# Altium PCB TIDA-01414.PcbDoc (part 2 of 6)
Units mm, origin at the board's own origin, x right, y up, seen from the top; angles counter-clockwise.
Board outline 400 x 135 mm, 4 copper layers (Top Copper, Copper Layer 2, Copper Layer 3, Bottom Copper), stack 1.567 mm thick; 835 components, 519 nets, 2420 pads, 2045 vias.
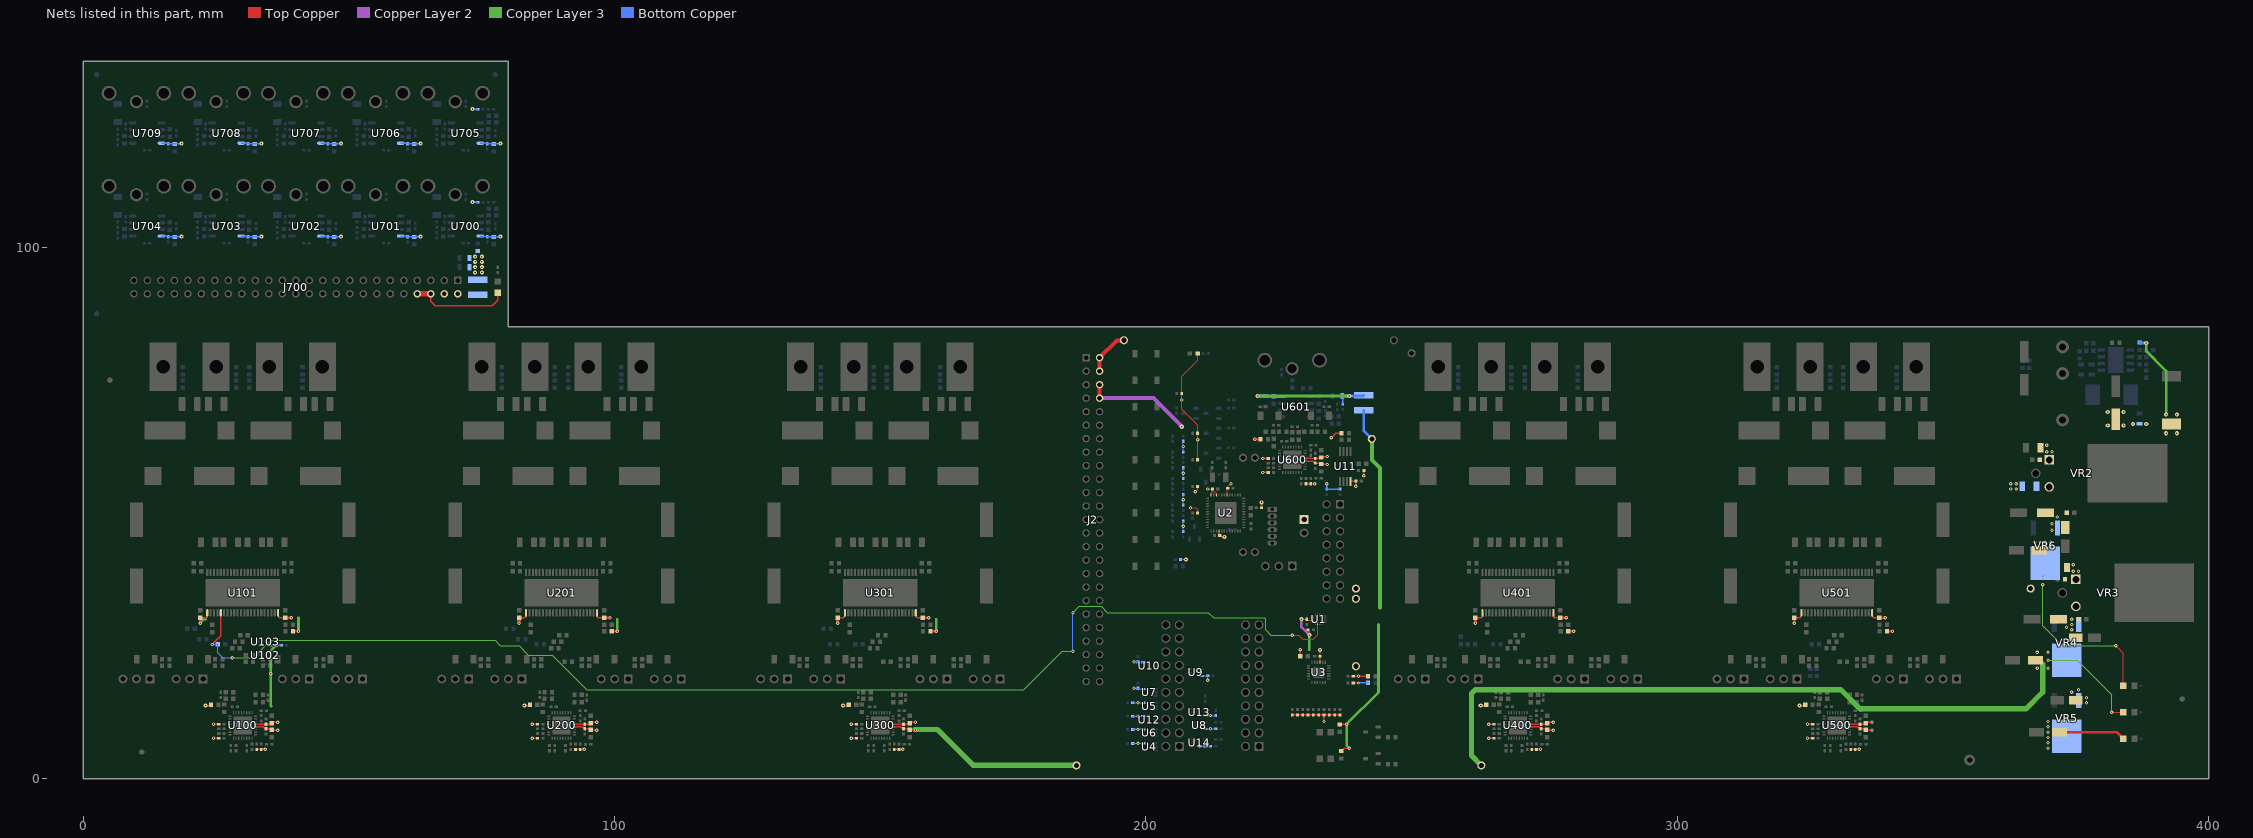
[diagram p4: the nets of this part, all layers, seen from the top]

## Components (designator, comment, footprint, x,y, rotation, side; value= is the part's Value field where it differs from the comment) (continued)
R705 "ERJ-2RKF1002X" 0402L 66.5,104.25 r90 bottom
R706 "ERJ-2RKF1002X" 0402L 51.5,104.25 r90 bottom locked
R707 "ERJ-2RKF1002X" 0402L 36.5,104.25 r90 bottom
R708 "ERJ-2RKF1002X" 0402L 21.5,104.25 r90 bottom
R709 "ERJ-2RKF1002X" 0402L 6.5,104.25 r90 bottom
R710 "ERJ-2RKF1002X" 0402L 72,100.75 r0 bottom
R711 "ERJ-2RKF1002X" 0402L 57,100.75 r0 bottom
R712 "ERJ-2RKF1002X" 0402L 42,100.75 r0 bottom
R713 "ERJ-2RKF1002X" 0402L 27,100.75 r0 bottom
R714 "ERJ-2RKF1002X" 0402L 12,100.75 r0 bottom
R715 "ERJ-2RKF1002X" 0402L 77.5,104 r90 bottom
R716 "ERJ-2RKF1002X" 0402L 62.5,104 r90 bottom locked
R717 "ERJ-2RKF1002X" 0402L 47.5,104 r90 bottom
R718 "ERJ-2RKF1002X" 0402L 32.5,104 r90 bottom
R719 "ERJ-2RKF1002X" 0402L 17.5,104 r90 bottom
R720 "ERJ-2RKF1002X" 0402L 66.5,119.75 r90 bottom
R721 "ERJ-2RKF1002X" 0402L 51.5,119.75 r90 bottom
R722 "ERJ-2RKF1002X" 0402L 36.5,119.75 r90 bottom
R723 "ERJ-2RKF1002X" 0402L 21.5,119.75 r90 bottom
R724 "ERJ-2RKF1002X" 0402L 6.5,119.75 r90 bottom
R725 "ERJ-2RKF1002X" 0402L 66.5,121.75 r90 bottom
R726 "ERJ-2RKF1002X" 0402L 51.5,121.75 r90 bottom
R727 "ERJ-2RKF1002X" 0402L 36.5,121.75 r90 bottom
R728 "ERJ-2RKF1002X" 0402L 21.5,121.75 r90 bottom
R729 "ERJ-2RKF1002X" 0402L 6.5,121.75 r90 bottom
R730 "ERJ-2RKF1002X" 0402L 72,118.25 r0 bottom
R731 "ERJ-2RKF1002X" 0402L 57,118.25 r0 bottom
R732 "ERJ-2RKF1002X" 0402L 42,118.25 r0 bottom
R733 "ERJ-2RKF1002X" 0402L 27,118.25 r0 bottom
R734 "ERJ-2RKF1002X" 0402L 12,118.25 r0 bottom
R735 "ERJ-2RKF1002X" 0402L 77.5,121.5 r90 bottom
R736 "ERJ-2RKF1002X" 0402L 62.5,121.5 r90 bottom
R737 "ERJ-2RKF1002X" 0402L 47.5,121.5 r90 bottom
R738 "ERJ-2RKF1002X" 0402L 32.5,121.5 r90 bottom
R739 "ERJ-2RKF1002X" 0402L 17.5,121.5 r90 bottom
R740 "ERJ-2RKF1002X" 0402L 74.75,108.5 r0 bottom
R741 "ERJ-2RKF1002X" 0402L 74.75,126 r0 bottom
R742 "ERJ-2RKF1002X" 0402L 76.75,108.5 r0 bottom
R743 "ERJ-2RKF1002X" 0402L 76.75,126 r0 bottom
R744 "CRCW0402100KFKED" 0402L 72,109.5 r90 bottom
R745 "CRCW0402100KFKED" 0402L 57,109.5 r90 bottom locked
R746 "CRCW0402100KFKED" 0402L 42,109.5 r90 bottom
R747 "CRCW0402100KFKED" 0402L 27,109.5 r90 bottom
R748 "CRCW0402100KFKED" 0402L 12,109.5 r90 bottom
R749 "CRCW0402100KFKED" 0402L 72,127 r90 bottom
R750 "CRCW0402100KFKED" 0402L 57,127 r90 bottom
R751 "CRCW0402100KFKED" 0402L 42,127 r90 bottom
R752 "CRCW0402100KFKED" 0402L 27,127 r90 bottom
R753 "CRCW0402100KFKED" 0402L 12,127 r90 bottom
R754 "CRCW0402360RJNED" 0402L 78,95.75 r90 top
RESET "TL1015AF160QG" SW_TL1015AF160QG 200,40 r180 top
SL+ "Surround Left+" TEC-SpadeLug_63066-1 45,77.5 r90 top
SL- "Surround Left-" TEC-SpadeLug_63066-1 35,77.5 r90 top
SR+ "Surround Right+" TEC-SpadeLug_63066-1 25,77.5 r90 top
SR- "Surround Right-" TEC-SpadeLug_63066-1 15,77.5 r90 top
SUBOUT "RCJ-024" CONN_RCJ-024 227.5,78.75 r180 top locked
SURROUND-LEFT "RCJ-024" CONN_RCJ-024 70,111.5 r180 top locked
SURROUND-RIGHT "RCJ-024" CONN_RCJ-024 70,129 r180 top locked
TP1 "FAULT" Keystone5003#1 355,3.5 r0 top
TP2 "CLIP" Keystone5003#2 372.5,67.5 r0 top
U1 "TCA6408ARSVR" RSV0016A 232.5,30 r90 top
U2 "MSP430F5234IRGZT" RGZ0048B 215,50 r270 top
U3 "TCA9548ARGER" RGE0024C 232.5,20 r0 top
U4 "LVC1G125" DCK0005A_N 200.625,6 r180 bottom
U5 "LVC1G125" DCK0005A_N 200.625,13.625 r180 bottom
U6 "LVC1G125" DCK0005A_N 200.625,8.625 r180 bottom
U7 "LVC1G125" DCK0005A_N 200.625,16.25 r180 bottom
U8 "LVC1G125" DCK0005A_N 210,10 r0 bottom
U9 "LVC1G125" DCK0005A_N 209.375,20 r0 bottom
U10 "LVC1G125" DCK0005A_N 200.6,21.25 r180 bottom
U11 "24LC512-I/ST" TSSOP-8 237.5,58.75 r270 top
U12 "LVC1G125" DCK0005A_N 200.625,11.125 r180 bottom
U13 "LVC1G125" DCK0005A_N 210,12.5 r0 bottom
U14 "LVC1G125" DCK0005A_N 210,6.75 r0 bottom
U100 "PCM5252RHBR" RHB0032E 30,10 r180 top locked
U101 "TPA3244DDWR" DDW0044D_N 30,35 r90 top locked
U102 "LVC1G125" DCK0005A_N 34.25,23.25 r0 bottom
U103 "LVC1G125" DCK0005A_N 34.25,25.75 r0 bottom
U200 "PCM5252RHBR" RHB0032E 90,10 r180 top locked
U201 "TPA3244DDWR" DDW0044D_N 90,35 r90 top
U300 "PCM5252RHBR" RHB0032E 150,10 r180 top locked
U301 "TPA3244DDWR" DDW0044D_N 150,35 r90 top
U400 "PCM5252RHBR" RHB0032E 270,10 r180 top locked
U401 "TPA3244DDWR" DDW0044D_N 270,35 r90 top
U500 "PCM5252RHBR" RHB0032E 330,10 r180 top
U501 "TPA3244DDWR" DDW0044D_N 330,35 r90 top
U600 "PCM5252RHBR" RHB0032E 227.5,60 r180 top
U601 "NE5532AD" D0008A_N 228.25,70 r180 bottom
U700 "NE5532AD" D0008A_N 72,104 r0 bottom
U701 "NE5532AD" D0008A_N 57,104 r0 bottom locked
U702 "NE5532AD" D0008A_N 42,104 r0 bottom
U703 "NE5532AD" D0008A_N 27,104 r0 bottom
U704 "NE5532AD" D0008A_N 12,104 r0 bottom
U705 "NE5532AD" D0008A_N 72,121.5 r0 bottom
U706 "NE5532AD" D0008A_N 57,121.5 r0 bottom
U707 "NE5532AD" D0008A_N 42,121.5 r0 bottom
U708 "NE5532AD" D0008A_N 27,121.5 r0 bottom
U709 "NE5532AD" D0008A_N 12,121.5 r0 bottom
UPL+ "Up Left+" TEC-SpadeLug_63066-1 105,77.5 r90 top
UPL- "Up Left-" TEC-SpadeLug_63066-1 95,77.5 r90 top
UPMIX-LEFT "RCJ-024" CONN_RCJ-024 55,111.5 r180 top locked
UPMIX-RIGHT "RCJ-024" CONN_RCJ-024 55,129 r180 top locked
UPR+ "Up Right+" TEC-SpadeLug_63066-1 85,77.5 r90 top
UPR- "Up Right-" TEC-SpadeLug_63066-1 75,77.5 r90 top
USB-I2X "PPPC082LFBN-RC" Sullins_xPxC082LFBN 235.25,42.75 r270 top
VOL-DN "" SW_TL1015AF160QG 200,70 r0 top
VOL-UP "" SW_TL1015AF160QG 200,75 r0 top
VR1 "TPS54340DDAR" DDA0008E_N 382.5,78.75 r0 bottom
VR2 "LM2940CT-12/NOPB" TO-220AB_Horizontal_100mil 370,60 r270 top locked
VR3 "LM2940CT-12/NOPB" TO-220AB_Horizontal_100mil 375,37.5 r270 top locked
VR4 "TLV1117-33IKVURG3" KVU0003A_N 373.25,24.75 r270 bottom
VR5 "TLV1117-33IKVURG3" KVU0003A_N 373.25,10.5 r270 bottom
VR6 "TLV1117-33IKVURG3" KVU0003A_N 369.25,43 r270 bottom
Y2 "NX3215SA-32.768K-STD-MUA-8" XTAL_NX3215SA 213.75,56.75 r180 top
ZZ1 "These assemblies must comply with workmanship standards IPC-A-610 Class 2, unless otherwise specified." AssemblyNote 4.25,140 r0 top
ZZ2 "These assemblies are ESD sensitive, ESD precautions shall be observed." AssemblyNote 4.25,144 r0 top
ZZ3 "These assemblies must be clean and free from flux and all contaminants. Use of no clean flux is not acceptable." AssemblyNote 4.25,142 r0 top

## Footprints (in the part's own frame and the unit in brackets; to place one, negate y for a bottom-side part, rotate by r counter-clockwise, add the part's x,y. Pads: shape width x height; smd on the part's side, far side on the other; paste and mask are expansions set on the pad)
3M_923345-20-C [mil] "Jumper Wire, 2\" Spacing, Red, Pkg of 100"
  round 60 hole 38: 1(-1000,0) 2(1000,0)
  silkscreen extent -970,-32 970,32, body extent -1015,-29 1013,29, height 79
3M_923345-30-C [mil] "Jumper Wire, 3\" Spacing, Orange, Pkg of 75"
  round 60 hole 38: 1(-1500,0) 2(1500,0)
  silkscreen extent -1470,-32 1470,32, body extent -1515,-27 1517,31, height 79
3M_923345-50-C [mil] "Jumper Wire, 5\" Spacing, Green, Pkg of 75"
  round 60 hole 38: 1(-2500,0) 2(2500,0)
  silkscreen extent -2470,-32 2470,32, body extent -2516,-29 2515,30, height 79
3M_N2550-6002-RB [mm] "Header, 2.54mm, 25x2, TH"
  rect 1.4x1.4 hole 0.89: 1(-1.27,30.48)
  round 1.4 hole 0.89: 2(1.27,30.48) 3(-1.27,27.94) 4(1.27,27.94) 5(-1.27,25.4) 6(1.27,25.4) 7(-1.27,22.86) 8(1.27,22.86) 9(-1.27,20.32) 10(1.27,20.32) 11(-1.27,17.78) 12(1.27,17.78) 13(-1.27,15.24) 14(1.27,15.24) 15(-1.27,12.7) 16(1.27,12.7) 17(-1.27,10.16) 18(1.27,10.16) 19(-1.27,7.62) 20(1.27,7.62) 21(-1.27,5.08) 22(1.27,5.08) 23(-1.27,2.54) 24(1.27,2.54) 25(-1.27,0) 26(1.27,0) 27(-1.27,-2.54) 28(1.27,-2.54) 29(-1.27,-5.08) 30(1.27,-5.08) 31(-1.27,-7.62) 32(1.27,-7.62) 33(-1.27,-10.16) 34(1.27,-10.16) 35(-1.27,-12.7) 36(1.27,-12.7) 37(-1.27,-15.24) 38(1.27,-15.24) 39(-1.27,-17.78) 40(1.27,-17.78) 41(-1.27,-20.32) 42(1.27,-20.32) 43(-1.27,-22.86) 44(1.27,-22.86) 45(-1.27,-25.4) 46(1.27,-25.4) 47(-1.27,-27.94) 48(1.27,-27.94) 49(-1.27,-30.48) 50(1.27,-30.48)
  silkscreen extent -4.5,-35.41 4.52,35.41, body extent -4.11,-35.41 4.52,35.41, height 9.92
0402L [mm] "0402 from SM-752 data"
  rect 0.6x0.5 smd: 1(-0.5,0) 2(0.5,0)
  body extent -0.55,-0.3 0.55,0.3, height 0.6
0603L [mm] "0603 from SM-752 data"
  rect 0.8x0.85 smd: 1(-0.7,0) 2(0.7,0)
  silkscreen extent -0.07,-0.33 0.07,0.33, body extent -0.87,-0.47 0.87,0.47, height 1
0805_KTR [mm] "ROHM"
  rect 0.7x1.15 smd: 1(-0.95,0) 2(0.95,0)
  silkscreen extent -0.35,-0.7 0.35,0.7, body extent -1.05,-0.67 1.05,0.67, height 0.65
1206_180 [mm] "1206_180"
  rect 1.1x1.6 smd: 1(-1.7,0) 2(1.7,0)
  silkscreen extent -0.9,-1 0.9,1, body extent -1.75,-0.95 1.75,0.95, height 1.8
1206_180L [mm] "1206_180"
  rect 1.1x1.75 smd: 1(-1.35,0) 2(1.35,0)
  silkscreen extent -0.4,-0.77 0.4,0.77, body extent -1.75,-0.95 1.75,0.95, height 1.8
1206L [mm] "1206 from SM-752 data"
  rect 1.1x1.75 smd: 1(-1.35,0) 2(1.35,0)
  silkscreen extent -0.4,-0.77 0.4,0.77, body extent -1.7,-0.9 1.7,0.9, height 1.35
1210_220 [mm] "1210"
  rect 1.3x2.7 smd: 1(-1.45,0) 2(1.45,0)
  silkscreen extent -2.32,-1.57 2.32,1.57, body extent -1.7,-1.35 1.7,1.35, height 2.2
AssemblyNote [mm] "Assembly Note"
Bivar_9912-250 [mm] "NYLON TUBE SPACER"
  body extent -3.17,-3.17 3.17,3.18, height 22.22
Coilcraft_RA7231-ALB [mm] "SMD, 4-Leads, Body 15.5x14mm"
  rect 7.7x3.4 smd: 1(-4.65,4.3) 3(4.65,-4.3)
  rect 3.2x3.4 smd: 2(-6.9,-4.3) 4(6.9,4.3)
  silkscreen extent -7.75,-7 7.75,7.4, body extent -7.75,-7 7.75,7, height 15.99
CONN_923345-07-C [mil] "3M, Wire jumper, 700 mil lenght, Violet"
  round 60 hole 37: 1(-350,0) 2(350,0)
  silkscreen extent -315,-35 315,31, body extent -363,-33 363,33, height 74
CONN_RCJ-024 [mm] "RCA Jack, Vertical, Yellow, TH"
  round 2.5 hole 1.7: 1(0,1.6)
  round 2.8 hole 2: 2(-5.15,0) 3(5.15,0)
  silkscreen extent -5.26,-5.1 5.46,4.9, body extent -6.38,-5.1 6.58,4.9, height 15.95
D0008A_N [mm] "SOIC, 8-Leads, Body 4.9x3.9mm, Pitch 1.27mm, IPC Medium Density"
  oval 1.45x0.6 smd: 1(-2.725,1.905) 2(-2.725,0.635) 3(-2.725,-0.635) 4(-2.725,-1.905) 5(2.725,-1.905) 6(2.725,-0.635) 7(2.725,0.635) 8(2.725,1.905)
  silkscreen extent -3.3,-2.5 0.9,2.5, body extent -3,-2.45 3,2.45, height 1.63
DCK0005A_N [mm] "SOT353, 5-Leads, Body 2x1.3mm, Pitch 0.65mm, Lead Span 2.1mm, IPC Medium Density"
  rrect25% 0.85x0.4 smd: 1(-1.125,0.65) 2(-1.125,0) 3(-1.125,-0.65) 4(1.125,-0.65) 5(1.125,0.65)
  silkscreen extent -1.48,-1.02 0.55,1.1, body extent -1.14,-1 1.14,1, height 0.95
DDA0008E_N [mm]
  rrect17% 1.45x0.6 smd: 1(-2.725,1.905) 2(-2.725,0.635) 3(-2.725,-0.635) 4(-2.725,-1.905) 5(2.725,-1.905) 6(2.725,-0.635) 7(2.725,0.635) 8(2.725,1.905)
  rrect7% 2.95x4.9 smd paste-1.5 mask-1.5: 9(0,0)
  rrect4% 2.4x3.1 on Bottom Paste: 9(0,0)
  rrect4% 2.4x3.1 on Bottom Solder: 9(0,0)
  silkscreen extent -3.22,-2.5 1.4,2.5, body extent -3,-2.45 3,2.45, height 1.57
DDW0044D_N [mm] "SOP, 44-Leads, Body 14.1x6.2mm, Pitch 0.635mm, IPC Medium Density"
  rrect100% 1.4x0.4 smd: 1(-3.8,6.667) 2(-3.8,6.032) 3(-3.8,5.397) 4(-3.8,4.763) 5(-3.8,4.127) 6(-3.8,3.492) 7(-3.8,2.857) 8(-3.8,2.222) 9(-3.8,1.587) 10(-3.8,0.952) 11(-3.8,0.317) 12(-3.8,-0.318) 13(-3.8,-0.953) 14(-3.8,-1.588) 15(-3.8,-2.223) 16(-3.8,-2.858) 17(-3.8,-3.492) 18(-3.8,-4.127) 19(-3.8,-4.763) 20(-3.8,-5.398) 21(-3.8,-6.033) 22(-3.8,-6.668) 23(3.8,-6.668) 24(3.8,-6.033) 25(3.8,-5.398) 26(3.8,-4.763) 27(3.8,-4.127) 28(3.8,-3.492) 29(3.8,-2.857) 30(3.8,-2.222) 31(3.8,-1.587) 32(3.8,-0.952) 33(3.8,-0.317) 34(3.8,0.318) 35(3.8,0.953) 36(3.8,1.588) 37(3.8,2.223) 38(3.8,2.858) 39(3.8,3.492) 40(3.8,4.127) 41(3.8,4.763) 42(3.8,5.397) 43(3.8,6.032) 44(3.8,6.667)
  rrect4% 5.2x14 smd paste-3 mask-3: 45(0,0)
  rrect2% 4.43x7.3 on Top Paste: 45(0,0)
  rrect2% 4.43x7.3 on Top Solder: 45(0,0)
  silkscreen extent -4.35,-7.05 2.7,7.12, body extent -4.06,-7 4.06,7, height 1
FCC_disclaimer_stacked [mm]
Fiducial10-20 [mm]
  round 1 smd mask+0.5: 1(0,0)
  Top Copper keep-out circle w1.178: c0,0 r0.5
Keystone5000 [mil] "For Keystone 500x miniature loop terminals"
  round 95 hole 50: 1(0,0)
  silkscreen extent -58,-58 58,58, body extent -49,-49 49,49, height 182
Keystone5001 [mil] "For Keystone 500x miniature loop terminals"
  round 95 hole 50: 1(0,0)
  silkscreen extent -58,-58 58,58, body extent -49,-49 49,49, height 182
Keystone5003#1 [mil] "For Keystone 500x miniature loop terminals"
  round 80 hole 40: 1(0,0)
  silkscreen extent -58,-58 58,58, body extent -49,-49 49,49, height 182
Keystone5003#2 [mil] "For Keystone 500x miniature loop terminals"
  round 95 hole 50: 1(0,0)
  silkscreen extent -58,-58 58,58, body extent -49,-49 49,49, height 182
Keystone_3205 [mm] "Flat Nylon Washer"
  body extent -3.96,-3.96 3.96,3.96, height 1.57
KVU0003A_N [mm] "DPAK, 3-Leads, Body 6.6x6.1mm, Pitch 2.29mm, IPC Medium Density"
  rrect10% 2.8x1 smd: 1(-4.2,2.29) 3(-4.2,-2.29)
  rrect2% 6.3x5.55 smd: 4(2.5,0)
  silkscreen extent -4.35,-3.35 -1.05,3.46, body extent -5.06,-3.3 5.06,3.3, height 2.39
LED_LTST-C170_Red [mm] "LITE-ON"
  rect 1.2x1.2 smd: 1(-1.05,0) 2(1.05,0)
  silkscreen extent -1.6,-1 2.2,1, body extent -1.05,-0.67 1.05,0.67, height 1.1
LED_LTST-C171 [mm] "LITE-ON"
  rect 1.2x1.2 smd: 1(-1.05,0) 2(1.05,0)
  silkscreen extent -1.6,-1 2.2,1, body extent -1.05,-0.67 1.05,0.67, height 0.8
LED_LTST-C190_Red [mm] "Lite-On"
  rect 0.8x0.8 smd: 1(-0.75,0) 2(0.75,0)
  silkscreen extent -1.1,-0.8 1.8,0.8, body extent -0.85,-0.45 0.85,0.45, height 0.9
LED_SMLP12_BLUE [mm] "Rohm Semiconductor"
  rect 0.5x0.6 smd mask+0.08: 1(-0.45,0) 2(0.45,0)
  silkscreen extent 0.92,-0.3 0.92,0.3, body extent -0.55,-0.35 0.55,0.35, height 0.25
LTST-C170KFKT_Orange [mm] "LITE-ON"
  rect 1.2x1.2 smd: 1(-1.05,0) 2(1.05,0)
  silkscreen extent -1.6,-1 2.2,1, body extent -1.05,-0.67 1.05,0.67, height 1.1
Mill-Max_851-XX-006-10-001000 [mil] "Mill-Max"
  rect 36x70 hole 26: 1(125,0)
  oval 36x70 hole 26: 2(75,0) 3(25,0) 4(-25,0) 5(-75,0) 6(-125,0)
  silkscreen extent -162,-50 177,50, body extent -160,-45 160,45, height 162
NRS4012 [mm] "2-Leads SMD, Body 4.2x4.2mm, Height 1.2mm"
  rect 1.2x3.7 smd: 1(-1.4,0) 2(1.4,0)
  silkscreen extent -0.49,-2.1 0.49,2.1, body extent -2.1,-2.1 2.1,2.1, height 1.2
Pb-Free_Overlay_Small [mm]
  silkscreen extent -1.16,-1.17 1.17,1.17
PBC03SAAN [mm] "Sullins 100mil, 1x3, 230 mil above insulator"
  rect 1.65x1.65 hole 1.016: 1(-2.54,0)
  round 1.65 hole 1.016: 2(0,0) 3(2.54,0)
  silkscreen extent -3.81,-1.27 3.81,1.27, body extent -3.81,-1.27 3.81,1.27, height 8.38
RGE0024C [mm] "QFN, 24-Leads, Body 4x4mm, Pitch 0.5mm, Thermal Pad 2.1x2.1mm"
  rrect40% 0.6x0.25 smd: 1(-1.9,1.25) 2(-1.9,0.75) 3(-1.9,0.25) 4(-1.9,-0.25) 5(-1.9,-0.75) 6(-1.9,-1.25) 13(1.9,-1.25) 14(1.9,-0.75) 15(1.9,-0.25) 16(1.9,0.25) 17(1.9,0.75) 18(1.9,1.25)
  rrect40% 0.25x0.6 smd: 7(-1.25,-1.9) 8(-0.75,-1.9) 9(-0.25,-1.9) 10(0.25,-1.9) 11(0.75,-1.9) 12(1.25,-1.9) 19(1.25,1.9) 20(0.75,1.9) 21(0.25,1.9) 22(-0.25,1.9) 23(-0.75,1.9) 24(-1.25,1.9)
  rrect11% 0.94x0.94 on Top Paste: 25(-0.57,-0.57) 25(-0.57,0.57) 25(0.57,-0.57) 25(0.57,0.57)
  rrect5% 2.1x2.1 smd paste-1.05: 25(0,0)
  silkscreen extent -2.22,-2.22 2.22,2.22, body extent -2.07,-2.07 2.07,2.07, height 1.01
RGZ0048B [mm] "QFN, 48-Leads, Body 7x7mm, Pitch 0.5mm, Thermal Pad 5.15x5.15mm, TI Recommended"
  oval 0.6x0.24 smd: 1(-3.4,2.75) 2(-3.4,2.25) 3(-3.4,1.75) 4(-3.4,1.25) 5(-3.4,0.75) 6(-3.4,0.25) 7(-3.4,-0.25) 8(-3.4,-0.75) 9(-3.4,-1.25) 10(-3.4,-1.75) 11(-3.4,-2.25) 12(-3.4,-2.75) 25(3.4,-2.75) 26(3.4,-2.25) 27(3.4,-1.75) 28(3.4,-1.25) 29(3.4,-0.75) 30(3.4,-0.25) 31(3.4,0.25) 32(3.4,0.75) 33(3.4,1.25) 34(3.4,1.75) 35(3.4,2.25) 36(3.4,2.75)
  oval 0.24x0.6 smd: 13(-2.75,-3.4) 14(-2.25,-3.4) 15(-1.75,-3.4) 16(-1.25,-3.4) 17(-0.75,-3.4) 18(-0.25,-3.4) 19(0.25,-3.4) 20(0.75,-3.4) 21(1.25,-3.4) 22(1.75,-3.4) 23(2.25,-3.4) 24(2.75,-3.4) 37(2.75,3.4) 38(2.25,3.4) 39(1.75,3.4) 40(1.25,3.4) 41(0.75,3.4) 42(0.25,3.4) 43(-0.25,3.4) 44(-0.75,3.4) 45(-1.25,3.4) 46(-1.75,3.4) 47(-2.25,3.4) 48(-2.75,3.4)
  rect 4.1x4.1 smd paste-2.575: 49(0,0)
  silkscreen extent -3.72,-3.72 3.72,3.72, body extent -3.57,-3.58 3.58,3.57, height 1.01
RHB0032E [mm] "QFN, 32-Leads, Body 5x5mm, Pitch 0.5mm, Thermal Pad 3.45x3.45mm, TI Recommended"
  oval 0.6x0.24 smd: 1(-2.4,1.75) 2(-2.4,1.25) 3(-2.4,0.75) 4(-2.4,0.25) 5(-2.4,-0.25) 6(-2.4,-0.75) 7(-2.4,-1.25) 8(-2.4,-1.75) 17(2.4,-1.75) 18(2.4,-1.25) 19(2.4,-0.75) 20(2.4,-0.25) 21(2.4,0.25) 22(2.4,0.75) 23(2.4,1.25) 24(2.4,1.75)
  oval 0.24x0.6 smd: 9(-1.75,-2.4) 10(-1.25,-2.4) 11(-0.75,-2.4) 12(-0.25,-2.4) 13(0.25,-2.4) 14(0.75,-2.4) 15(1.25,-2.4) 16(1.75,-2.4) 25(1.75,2.4) 26(1.25,2.4) 27(0.75,2.4) 28(0.25,2.4) 29(-0.25,2.4) 30(-0.75,2.4) 31(-1.25,2.4) 32(-1.75,2.4)
  rect 3.45x3.45 smd paste-1.725: 33(0,0)
  silkscreen extent -2.72,-2.73 2.72,2.73, body extent -2.57,-2.57 2.58,2.58, height 1.01
RSV0016A [mm] "QFN, 16-Leads, Body 1.8x2.6mm, Pitch 0.4mm, TI Recommended"
  rect 0.7x0.2 smd: 1(-0.75,0.6)
  rect 0.6x0.2 smd: 2(-0.8,0.2) 3(-0.8,-0.2) 4(-0.8,-0.6) 9(0.8,-0.6) 10(0.8,-0.2) 11(0.8,0.2) 12(0.8,0.6)
  rect 0.2x0.6 smd: 5(-0.6,-1.2) 6(-0.2,-1.2) 7(0.2,-1.2) 8(0.6,-1.2) 13(0.6,1.2) 14(0.2,1.2) 15(-0.2,1.2) 16(-0.6,1.2)
  silkscreen extent -1.08,-1.33 1.08,1.45, body extent -0.92,-1.32 0.92,1.33, height 0.56
SM_RADIAL_B [mm] "4 x 5.8mm:  Panasonic B"
  rect 2.5x1.6 smd: 1(-1.75,0) 2(1.75,0)
  silkscreen extent -2.24,-2.25 2.25,2.25, body extent -2.25,-2.25 2.25,2.25, height 6.1
SM_RADIAL_C [mm] "5 x 5.8mm:  Panasonic C"
  rect 2.8x1.6 smd: 1(-2.15,0) 2(2.15,0)
  silkscreen extent -2.75,-2.75 2.75,2.75, body extent -2.75,-2.75 2.75,2.75, height 6.1
SM_RADIAL_D [mm] "6.3 x 5.8mm:  Panasonic D"
  rect 3.2x1.6 smd: 1(-2.5,0) 2(2.5,0)
  silkscreen extent -3.4,-3.4 3.4,3.4, body extent -3.4,-3.4 3.4,3.4, height 6.1
SM_RADIAL_E [mm] "8 x 6.2mm:  Panasonic E"
  rect 4x1.6 smd: 1(-3.1,0) 2(3.1,0)
  silkscreen extent -4.25,-4.25 4.25,4.25, body extent -4.25,-4.25 4.25,4.25, height 6.5
SM_RADIAL_J16 [mm] "16 x 16.5mm:  Panasonic J16"
  rect 6.5x2.5 smd: 1(-6.25,0) 2(6.25,0)
  silkscreen extent -8.6,-8.6 8.6,8.6, body extent -8.6,-8.6 8.6,8.6, height 17
SMC [mil] "Molded Diode, 2-Leads, Body 6.9x5.8mm, IPC Medium Density, based on OnSemi component dimensions and land patterns"
  rect 110x150 smd: 1(-140.49,0) 2(140.49,0)
  silkscreen extent -221,-120 189,123, body extent -156,-116 156,116, height 91
SOT-23 [mm] "SOT23, 3-Leads, Body 2.9x1.3mm, Pitch 0.95mm, Lead Span 2.5mm, IPC Medium Density"
  rrect50% 1x0.6 smd: 1(-1.2,0.95) 2(-1.2,-0.95) 3(1.2,0)
  silkscreen extent -1.62,-1.5 0.7,1.5, body extent -1.16,-1.45 1.21,1.45, height 1
Sullins_PBC02SAAN [mm] "Sullins 100mil, 1x2, 230 mil above insulator"
  rect 1.65x1.65 hole 1.016: 1(0,1.27)
  round 1.65 hole 1.016: 2(0,-1.27)
  silkscreen extent -1.37,-2.54 1.27,3.1, body extent -1.27,-2.54 1.27,2.54, height 8.38
Sullins_SBH11-xxxC-D10-ST [mm] "Header (Shrouded), 2.54mm, 10x2, TH"
  rect 1.7x1.7 hole 1.2: 1(-1.27,11.43)
  round 1.7 hole 1.2: 2(1.27,11.43) 3(-1.27,8.89) 4(1.27,8.89) 5(-1.27,6.35) 6(1.27,6.35) 7(-1.27,3.81) 8(1.27,3.81) 9(-1.27,1.27) 10(1.27,1.27) 11(-1.27,-1.27) 12(1.27,-1.27) 13(-1.27,-3.81) 14(1.27,-3.81) 15(-1.27,-6.35) 16(1.27,-6.35) 17(-1.27,-8.89) 18(1.27,-8.89) 19(-1.27,-11.43) 20(1.27,-11.43)
  silkscreen extent -5.25,-16.45 4.4,16.45, body extent -4.4,-16.45 4.7,16.45, height 9.11
Sullins_xPxC082LFBN [mm] "Receptacle, 2.54mm, 8x2, TH"
  rect 1.55x1.55 hole 1.02: 1(-8.89,1.27)
  round 1.55 hole 1.02: 2(-8.89,-1.27) 3(-6.35,1.27) 4(-6.35,-1.27) 5(-3.81,1.27) 6(-3.81,-1.27) 7(-1.27,1.27) 8(-1.27,-1.27) 9(1.27,1.27) 10(1.27,-1.27) 11(3.81,1.27) 12(3.81,-1.27) 13(6.35,1.27) 14(6.35,-1.27) 15(8.89,1.27) 16(8.89,-1.27)
  silkscreen extent -10.41,-2.54 10.41,2.88, body extent -10.41,-2.54 10.41,2.54, height 8.5
SW_TL1015AF160QG [mm] "E-Switch"
  rect 0.95x1.4 smd: 1(-2.1,0) 2(2.1,0)
  silkscreen extent -2,-1.5 2,1.5, body extent -2.3,-1.5 2.3,1.5, height 2
TEC-SpadeLug_63066-1 [mil] "TE Connectivity"
  rect 360x200 hole 100: 1(0,0)
  silkscreen extent -190,-110 190,110, body extent -165,-96 165,96, height 430
TO-220AB_Horizontal_100mil [mm] "High Voltage staggered pins"
  rect 1.8x1.8 hole 1.3: 1(0,0)
  rect 11x15 smd: 2(2.54,14.732)
  round 1.8 hole 1.3: 2(2.54,-2.54) 3(5.08,0)
  body extent -2.8,-2.85 7.87,22.22, height 4.85
TSSOP-8 [mm] "TSSOP, 8-Leads, Body 3.1x4.5mm (max), Pitch 0.65mm, IPC Medium Density"
  rrect50% 1.7x0.35 smd: 1(-2.85,0.975) 2(-2.85,0.325) 3(-2.85,-0.325) 4(-2.85,-0.975) 5(2.85,-0.975) 6(2.85,-0.325) 7(2.85,0.325) 8(2.85,0.975)
  silkscreen extent -2.97,-1.55 1.6,1.83, body extent -3.2,-1.55 3.2,1.55, height 1.07
WE-PD_1050 [mm] "WERTH"
  rect 2x3.5 smd: 1(-4.5,0) 2(4.5,0)
  silkscreen extent -5,-5 5,5, body extent -5,-5 5,5, height 4.75
WireJumper_923345-05-C [mil] "Wire Jumper 500mil"
  round 60 hole 38: 1(-250,0) 2(250,0)
  silkscreen extent -200,-35 200,33, body extent -263,-33 263,33, height 71
XTAL_NX3215SA [mm] "NDK recommended land pattern"
  rect 1x1.8 smd: 1(-1.25,0) 2(1.25,0)
  silkscreen extent -0.6,-1.1 0.6,1.1, body extent -1.65,-0.8 1.65,0.8, height 0.9

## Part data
C1 C16 C22 C101 C112 C124 C142 C201 C212 C224 C242 C301 C312 C324 C342 C401 C412 C424 C442 C501 C512 C524 C542 C619 C712: "CAP, CERM, 0.1 µF, 50 V, +/- 10%, X7R, 0603"
C2 C620 C727 C728 C729 C730 C731 C737 C738 C739 C740 C741 C742 C743 C744 C745 C746 C752 C753 C754 C755 C756: "CAP, CERM, 22 pF, 50 V, +/- 5%, C0G/NP0, 0603"
C3 C5: library part EEE-FK1H470P, "CAP, AL, 47 µF, 50 V, +/- 20%, 0.68 ohm, SMD"
C4 C9 C10: "CAP, CERM, 2.2 µF, 50 V, +/- 10%, X7R, 0805"
C6: "CAP, CERM, 1 µF, 50 V, +/- 10%, X7R, 0603"
C7: "CAP, CERM, 75 pF, 50 V, +/- 5%, C0G/NP0, 0603"
C8 C116 C127 C136 C141 C216 C227 C236 C241 C316 C327 C336 C341 C416 C427 C436 C441 C516 C527 C536 C541: "CAP, CERM, 0.01 µF, 50 V, +/- 10%, X7R, 0603"
C11 C17: library part EEE-FK1C470P, "CAP, AL, 47 µF, 16 V, +/- 20%, 0.36 ohm, SMD"
C12 C18 C23: library part EEE-FK1C100R, "CAP, AL, 10 µF, 16 V, +/- 20%, 1.35 ohm, SMD"
C13 C19 C24: library part EEE-FK0J101UR, "CAP, AL, 100 µF, 6.3 V, +/- 20%, 0.7 ohm, SMD"
C14 C20: "CAP, CERM, 4.7 µF, 25 V, +/- 10%, X7R, 1206"
C15 C21: "CAP, CERM, 0.47 µF, 25 V, +/- 10%, X7R, 0603"
C25 C26 C48 C49 C50 C51 C53 C57: "CAP, CERM, 470 pF, 25 V, +/- 5%, C0G/NP0, 0402"
C27: "CAP, CERM, 3600 pF, 50 V, +/- 5%, C0G/NP0, 0603"
C28 C52: "CAP, CERM, 2200 pF, 16 V, +/- 10%, X7R, 0603"
C29 C30 C31 C32 C33 C34 C36 C37 C38 C43 C44 C45 C46 C56 C105 C107 C109 C130 C144 C145 C205 C207 C209 C230 C305 C307 C309 C330 C405 C407 C409 C430 C505 C507 C509 C530 C602 C604 C606 C616 C732 C733 C734 C735 C736 C747 C748 C749 C750 C751 C757 C758 C759 C760 C761 C762 C763 C764 C765 C766: "CAP, CERM, 0.1 µF, 10 V, +/- 10%, X7R, 0402"
C35 C55: "CAP, CERM, 1 µF, 6.3 V, +/- 20%, X5R, 0402"
C58 C59: "CAP, CERM, 12 pF, 50 V, +/- 5%, C0G/NP0, 0402"
C100 C111 C200 C211 C300 C311 C400 C411 C500 C511: library part EEV-FK1H102M, "CAP, AL, 1000 µF, 50 V, +/- 20%, 0.073 ohm, AEC-Q200 Grade 2, SMD"
C102 C103 C113 C114 C202 C203 C213 C214 C302 C303 C313 C314 C402 C403 C413 C414 C502 C503 C513 C514: "CAP, CERM, 1 µF, 50 V, +/- 10%, X7R, 1206"
C104 C106 C108 C204 C206 C208 C304 C306 C308 C404 C406 C408 C504 C506 C508 C601 C603 C605: "CAP, CERM, 10 µF, 10 V, +/- 20%, X5R, 0603"
C110 C119 C129 C134 C210 C219 C229 C234 C310 C319 C329 C334 C410 C419 C429 C434 C510 C519 C529 C534 C600 C610 C700 C701 C702 C703 C704 C705 C706 C707 C708 C709: "CAP, CERM, 10 µF, 16 V, +/- 10%, X7R, 1206"
C115 C126 C135 C140 C215 C226 C235 C240 C315 C326 C335 C340 C415 C426 C435 C440 C515 C526 C535 C540: "CAP, CERM, 1 µF, 100 V, +/- 10%, X7R, 1210"
C117 C121 C217 C221 C317 C321 C417 C421 C517 C521 C609: "CAP, CERM, 1000 pF, 50 V, +/- 5%, C0G/NP0, 0402"
C118 C125 C131 C137 C218 C225 C231 C237 C318 C325 C331 C337 C418 C425 C431 C437 C518 C525 C531 C537 C607 C612: "CAP, CERM, 100 pF, 50 V, +/- 5%, C0G/NP0, 0603"
C120 C123 C138 C139 C220 C223 C238 C239 C320 C323 C338 C339 C420 C423 C438 C439 C520 C523 C538 C539: "CAP, CERM, 0.033 µF, 25 V, +/- 10%, X7R, 0603"
C122 C128 C222 C228 C322 C328 C422 C428 C522 C528 C611 C613: "CAP, CERM, 2.2 µF, 10 V, +/- 10%, X5R, 0402"
C132 C133 C232 C233 C332 C333 C432 C433 C532 C533: "CAP, CERM, 1 µF, 16 V, +/- 10%, X7R, 0603"
C143 C243 C343 C443 C543: "CAP, CERM, 0.047 µF, 50 V, +/- 10%, X7R, 0603"
C608 C614 C615 C713 C714 C715 C716 C717 C718 C719 C720 C721 C722 C723 C724 C725 C726: "CAP, CERM, 10 µF, 16 V, +/- 20%, X5R, 0603"
C617 C618 C710 C711: "CAP, CERM, 10 µF, 16 V, +/- 10%, X5R, 0805"
CENTER-TWEETER CENTER-WOOFER FL-TWEETER FL-WOOFER FR-TWEETER FR-WOOFER SUBOUT SURROUND-LEFT SURROUND-RIGHT UPMIX-LEFT UPMIX-RIGHT: "RCA Jack, Vertical, Yellow, TH"
CT+ CT- CW+ CW- FLT+ FLT- FLW+ FLW- FRT+ FRT- FRW+ FRW- SL+ SL- SR+ SR- UPL+ UPL- UPR+ UPR-: library part 63066-1, "PC Quick-Fit 0.250 Tab, Vertical, TH"
D1 D2 D3 D4 D5: library part SMLP12BC7TT86, "LED, Blue, SMD"
D6: library part LTST-C190CKT, "LED, Red, SMD"
D12: "Diode, Schottky, 60 V, 5 A, SMC"
D13 D14 D15 D700: library part LTST-C171GKT, "LED, Green, SMD"
DIN2-SEL JP100 JP101 JP102 JP103 JP200 JP201 JP202 JP203 JP300 JP301 JP302 JP303 JP400 JP401 JP402 JP403 JP500 JP501 JP502 JP503: library part SIP3-90_PBC03SAAN, "Header, 100mil, 3x1, Gold, TH"
FAULT: library part LTST-C170KRKT, "LED, Red, SMD"
FID1 FID2 FID3 FID4 FID5 FID6 FID7 FID8 FID9: "Fiducial mark.  There is nothing to buy or mount."
GND-IN: library part 5001, "Test Point, Miniature, Black, TH"
H1 H2 H3 H4 H5 H6 H7 H8 H9: library part 9912-250, "NYLON TUBE SPACER"
H10 H11 H12 H13 H14 H15 H16 H17 H18: library part 3205, "Flat Nylon Washer"
I2S-IN: library part SBH11-PBPC-D10-ST-BK, "Header (Shrouded), 2.54mm, 10x2, Gold, Black, TH"
I2S-OUT: "Header (Shrouded), 2.54mm, 10x2, Gold, Black, TH"
J1: library part 923345-05-C, "Jumper Wire, 500mil spacing, Green, pkg of 200"
J2 J700: library part N2550-6002-RB, "Header(Shrouded), 2.54mm, 25x2, Gold, TH"
J4 J600 J601: library part 923345-07-C, "Jumper Wire, 700mil spacing, Violet, pkg of 150, TH"
J5: library part 923345-20-C, "Jumper Wire, 2\" spacing, Red, pkg of 100, TH"
J6: library part 923345-30-C, "Jumper Wire, 3\" spacing, Orange, pkg of 75, TH"
J8: library part 923345-50-C, "Jumper Wire, 5\" spacing, Green, pkg of 75, TH"
J11: "Header, 100mil, 2x1, Gold, TH"
JTAG: "Receptacle, 50mil, 6x1, Gold, TH"
L1: "Inductor, Shielded Drum Core, Ferrite, 100 µH, 1.5 A, 0.165 ohm, SMD"
L100 L200 L300 L400 L500: "Inductor, Wirewound, 10 µH, 0.08 A, 0.36 ohm, SMD"
L101 L102 L201 L202 L301 L302 L401 L402 L501 L502: "Coupled inductor, 10 µH, 6.6 A, SMD"
L600 L700: "Inductor, Wirewound, 10 µH, 0.8 A, 0.204 ohm, SMD"
LOAD MODE1 MODE2 MODE3 MODE4 MUTE VOL-DN VOL-UP: library part TL1015AF160QG, "Switch, Tactile, SPST-NO, 0.05A, 12V, SMT"
Logo2 Logo5: library part Pb-Free
Logo3 Logo6: library part FCC_disclaimer, "FCC_disclaimer"
OTW: library part LTST-C170KFKT, "LED, Orange, SMD"
PWR-IN: library part 5000, "Test Point, Miniature, Red, TH"
Q1 Q3: "MOSFET, N-CH, 60 V, 0.17 A, SOT-23"
Q2 Q4 Q5 Q6 Q7 Q8: library part "MMBT2222A, Fairchild Semiconductor", "Transistor, NPN, 40 V, 0.15 A, SOT-23"
R1 R64 R619 R620 R744 R745 R746 R747 R748 R749 R750 R751 R752 R753: "RES, 100 k, 1%, 0.063 W, 0402"
R2 R21 R22 R23 R24 R25 R29 R30 R31 R32 R33 R93: "RES, 0, 5%, 0.1 W, 0603"
R3 R4 R5 R6 R7 R8 R9 R10 R11 R12 R13 R14 R15 R16: "RES, 2.00 k, 1%, 0.1 W, AEC-Q200 Grade 0, 0402"
R17: "RES, 30.0 k, 1%, 0.1 W, 0603"
R18 R26: "RES, 1.00 k, 1%, 0.1 W, 0603"
R19 R27: "RES, 47 k, 5%, 0.1 W, 0603"
R20 R28 R102 R106 R108 R116 R202 R206 R208 R216 R302 R306 R308 R316 R402 R406 R408 R416 R502 R506 R508 R516 R603 R608: "RES, 100, 1%, 0.1 W, 0603"
R34: "RES, 215 k, 1%, 0.1 W, 0603"
R35: library part CRCW0603365KFKEA, "RES, 365 k, 1%, 0.1 W, 0603"
R36: "RES, 25.5 k, 1%, 0.1 W, 0603"
R37: "RES, 12.1 k, 1%, 0.1 W, 0603"
R38 R39 R40 R42 R44 R45 R60 R61: "RES, 33.2 k, 1%, 0.063 W, 0402"
R41 R74: "RES, 47.5 k, 1%, 0.063 W, 0402"
R43: "RES, 332, 1%, 0.063 W, 0402"
R46 R62 R65 R68 R70 R72: "RES, 100, 1%, 0.1 W, 0402"
R47: library part CRCW060386K6FKEA, "RES, 86.6 k, 1%, 0.1 W, 0603"
R48: "RES, 150 k, 1%, 0.1 W, 0603"
R49: "RES, 0, 5%, 0.25 W, 1206"
R50 R63 R67 R69 R71 R73: "RES, 2.15 k, 1%, 0.063 W, 0402"
R51 R52 R53 R754: "RES, 360, 5%, 0.063 W, 0402"
R54 R55 R56 R57 R58 R66: "RES, 10.0 k, 1%, 0.1 W, 0603"
R59: "RES, 10.0k ohm, 1%, 0.063W, 0402"
R75 R76 R77 R78 R79 R80 R81 R82 R83 R84 R85 R86 R87 R88 R89 R90 R91 R92: "RES, 49.9, 1%, 0.063 W, 0402"
R94: library part CRCW06030000Z0EA, "RES, 0, 5%, 0.1 W, 0603"
R100 R200 R300 R400 R500 R601: "RES, 10, 5%, 0.1 W, 0603"
R101 R103 R105 R107 R201 R203 R205 R207 R301 R303 R305 R307 R401 R403 R405 R407 R501 R503 R505 R507 R602 R607: "RES, 499, 1%, 0.1 W, 0603"
R104 R109 R118 R120 R204 R209 R218 R220 R304 R309 R318 R320 R404 R409 R418 R420 R504 R509 R518 R520: "RES, 3.3, 5%, 0.1 W, 0603"
R110 R111 R210 R211 R310 R311 R410 R411 R510 R511 R612 R613: library part ERJ-2RKF1002X, "RES, 10.0 k, 1%, 0.1 W, 0402"
R112 R113 R114 R212 R213 R214 R312 R313 R314 R412 R413 R414 R512 R513 R514 R600 R604 R606 R609 R610 R611 R614 R615 R616 R700 R701 R702 R703 R704 R705 R706 R707 R708 R709 R710 R711 R712 R713 R714 R715 R716 R717 R718 R719 R720 R721 R722 R723 R724 R725 R726 R727 R728 R729 R730 R731 R732 R733 R734 R735 R736 R737 R738 R739 R740 R741 R742 R743: "RES, 10.0 k, 1%, 0.1 W, 0402"
R115 R117 R215 R217 R315 R317 R415 R417 R515 R517 R617 R618: "RES, 4.99 k, 1%, 0.063 W, 0402"
R119 R219 R319 R419 R519: "RES, 22.0 k, 1%, 0.1 W, 0603"
R605: "RES, 49.9, 1%, 0.1 W, 0603"
RESET: "Switch, Tactile, SPST-NO, 0.05A, 12V, SMT"
TP1 TP2: library part 5003, "Test Point, Miniature, Orange, TH"
U1: "Low-Voltage 8-Bit I2C and SMBus I/O Expander, 1.65 to 5.5 V, -40 to 85 degC, 16-pin UQFN (RSV), Green (RoHS & no Sb/Br)"
U2: "Mixed Signal Microcontroller, RGZ0048B (VQFN-48)"
U3: "8-Channel I2C Switch With Reset, RGE0024C (VQFN-24)"
U4 U5 U6 U7 U8 U9 U10 U12 U13 U14 U102 U103: library part SN74LVC1G125DCKR, "Single Bus Buffer Gate With 3-State Output, DCK0005A"
U11: "EEPROM, 512KBIT, 400KHZ, 8TSSOP"
U100 U200 U300 U400 U500 U600: "4.2VRMS DirectPath™, 114dB Audio Stereo Differential-Output DAC with 32-bit, 384kHz PCM Interface, RHB0032E"
U101 U201 U301 U401 U501: "40-W Stereo, 100-W peak PurePath™ Ultra-HD Pad Down Class-D Amplifier, DDW0044D"
U601 U700 U701 U702 U703 U704 U705 U706 U707 U708 U709: "Dual Low-Noise Operational Amplifier, 10 to 30 V, 0 to 70 degC, 8-pin SOIC (D0008A), Green (RoHS & no Sb/Br)"
USB-I2X: "Receptacle, 2.54mm, 8x2, Gold, TH"
VR1: "42 V Input, 3.5 A, Step Down DC-DC Converter with Eco-mode, DDA0008E (SOIC-8)"
VR2 VR3: "1A Low Dropout Regulator, 3-pin TO-220, Pb-Free"
VR4 VR5 VR6: "FIXED LOW-DROPOUT VOLTAGE REGULATOR, KVU0003A (TO-252-3)"
Y2: "Crystal, 32.768kHz, 12.5pF, SMD"
ZZ1 ZZ2 ZZ3: library part AssemblyNote

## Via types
v1: diameter 0.635, hole 0.254, Top Copper to Bottom Copper, tented both sides, 1429 vias
v2: diameter 0.762, hole 0.254, Top Copper to Bottom Copper, tented both sides, 311 vias
v3: diameter 0.5, hole 0.2, Top Copper to Bottom Copper, 150 vias
v4: diameter 0.5, hole 0.2, Top Copper to Bottom Copper, tented both sides, 124 vias
v5: diameter 0.508, hole 0.254, Top Copper to Bottom Copper, tented both sides, 21 vias
v6: diameter 6.5, hole 4.5, Top Copper to Bottom Copper, tented both sides, 9 vias
v7: diameter 0.889, hole 0.254, Top Copper to Bottom Copper, tented both sides, 1 vias

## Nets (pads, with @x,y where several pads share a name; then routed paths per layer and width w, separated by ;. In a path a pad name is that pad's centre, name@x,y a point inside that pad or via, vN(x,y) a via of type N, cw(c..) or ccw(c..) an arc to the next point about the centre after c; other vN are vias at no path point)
3.3V: C31.2 C32.2 C33.2 C34.2 C603.1 C604.1 C605.1 C606.1 D1.1 D2.1 D3.1 D4.1 D5.1 D6.1 J1.1 J2.6 J2.8 J8.1 J11.1 R12.1 R13.1 R38.1 R39.1 R40.1 R41.2 R42.1 R44.1 R45.1 R60.1 R61.1 R64.2 R74.2 R93.2 R601.1 R612.2 R613.2 R614.1 R618.2 U2.6 U2.10 U2.12 U2.28 U11.8 U600.4 U600.5 | length 86
  Top Copper w0.2: v1(208.375,51) 209.375,51 209.7,50.675 D3.1@209.7,50 ; v1(209.25,54) 209.7,54.45 D2.1@209.7,55 ; D1.1@209.7,60 209.75,60.05 v1(209.75,63.75) 209.75,64.95 D5.1@209.7,65 209.7,66.55 206.75,69.5 v1(206.75,71.25) 206.75,72.45 D4.1@206.7,72.5 206.7,75.7 209.75,78.75 D6.1@209.75,80 ; v1(211.625,54.5) C34.2@212.5,54.5 212.5,54 ; U2.12@212.25,53.4 212.25,53.75 212.5,54 ; U2.10@213.25,53.375 U2.10@213.25,53.4 213.25,53.75 213.125,53.875 213,54 212.5,54 ; U2.6@215.25,53.4 215.25,54.5 C33.2@215.375,54.625 ; C33.2@215.5,54.625 215.5,55 v1(216,55.5)
  Top Copper w0.25: U2.28@213.75,46.6 213.75,45.875 C32.2@213.875,45.75 214.125,45.5 v2(214.75,45.5) ; R41.2@221.75,51 v2(221.75,52) ; v1(222,57.625) R618.2@223,57.625 ; v1(222,60.25) R613.2@223,60.25 ; U600.4@229.9,59.75 231.375,59.75 231.75,59.375 232.825,59.375 233.075,59.125 v1(234.125,59.125) ; U600.5@229.9,60.25 C604.1@231.875,60.25 232.825,60.25 233.2,60.625 v1(234.125,60.625) ; R612.2@230.125,55.5 R614.1@231,55.5 v1(231.75,55.5) ; v1(234.875,64.125) 235.75,65 R93.2@236.8,65 ; U11.8@238.5,56 C31.2@239.5,56 v1(239.5,55) ; v1(241,57) R64.2@241,58
  Top Copper w0.5: v1(220.5,63.875) R601.1@221.55,63.875
  Top Copper w0.75: J2.8@191.27,71.61 J2.6@191.27,74.15
  Copper Layer 2 w0.75: J2.8@191.27,71.61 201.39,71.61 v7(206.75,66.25)
  Bottom Copper w0.2: R74.2@206.5,41.25 v2(207.5,41.25) ; R45.1@207,46.5 v1(207,47.5) R61.1@207,48.5 ; R60.1@207,51.5 v1(207,52.5) R44.1@207,53.5 ; R42.1@207,56.5 v1(207,57.5) R40.1@207,58.5 ; R39.1@207,61.5 v1(207,62.5) R38.1@207,63.5
  Bottom Copper w0.25: v1(234,55.5) R13.1@234,54.5 R12.1@236.5,54.5
3.3V-1: C19.1 D14.1 J6.1 VR4.4 | length 150.3
  Top Copper w0.2: v1(381.75,12.5) D14.1@383.95,12.5
  Copper Layer 3 w0.2: v1(369.75,22.25) 375.25,22.25 381.75,15.75 v1(381.75,12.5)
  Copper Layer 3 w1: J6.1@263.1,2.5 261.25,4.35 261.25,16 262,16.75 330.75,16.75 334.375,13.125 365.625,13.125 368.75,16.25 368.75,21.5
  other v1: 367.75,20.75 369.75,20.75 367.75,23.75 369.75,23.75
3.3V-2: C24.1 C406.1 C407.1 C408.1 C409.1 C506.1 C507.1 C508.1 C509.1 D15.1 R400.1 R410.2 R411.2 R412.1 R417.2 R500.1 R510.2 R511.2 R512.1 R517.2 U400.4 U400.5 U500.4 U500.5 VR5.4 | length 39.6
  Top Copper w0.25: v2(263,13.75) 263.925,13.75 R400.1@264.05,13.875 ; v1(264.5,7.625) R417.2@265.5,7.625 ; v1(264.5,10.25) R411.2@265.5,10.25 ; U400.4@272.4,9.75 273.875,9.75 274.25,9.375 275.325,9.375 C408.1@275.5,9.2 275.575,9.125 v1(276.625,9.125) ; U400.5@272.4,10.25 C407.1@274.375,10.25 275.325,10.25 C406.1@275.5,10.425 275.7,10.625 v1(276.625,10.625) ; R410.2@272.625,5.5 R412.1@273.5,5.5 v1(274.25,5.5) ; v2(323,13.75) 323.925,13.75 R500.1@324.05,13.875 ; v1(324.5,7.625) R517.2@325.5,7.625 ; v1(324.5,10.25) R511.2@325.5,10.25 ; U500.4@332.4,9.75 333.875,9.75 334.25,9.375 335.325,9.375 C508.1@335.5,9.2 335.575,9.125 v1(336.625,9.125) ; U500.5@332.4,10.25 C507.1@334.375,10.25 335.325,10.25 C506.1@335.5,10.425 335.7,10.625 v1(336.625,10.625) ; R510.2@332.625,5.5 R512.1@333.5,5.5 v1(334.25,5.5)
  Top Copper w0.5: C24.1@372,8.75 382.7,8.75 D15.1@383.95,7.5
  other v1: 369.75,5.75 369.75,6.75 369.75,7.75 369.75,8.75 369.75,9.75 369.75,10.75
3.3V-3: C29.2 C30.2 C35.2 C36.2 C37.2 C38.2 C43.2 C44.2 C45.2 C46.2 C55.2 C56.2 J1.2 R3.2 R4.2 R5.2 R6.2 R7.2 R8.2 R9.2 R10.2 R11.2 R14.2 R15.2 R16.2 R19.2 R27.2 R59.1 R66.2 U1.14 U1.15 U3.21 U4.5 U5.5 U6.5 U7.5 U8.5 U9.5 U10.5 U12.5 U13.5 U14.5 | length 49.3
  Top Copper w0.2: v2(229.25,30) C30.2@230.25,30 230.45,29.8 U1.15@231.3,29.8 U1.14@231.3,30.2 ; U3.21@232.75,21.75 C29.2@232.75,23 v2(232.75,24.25)
  Top Copper w0.25: R16.2@227.5,12 R15.2@228.5,12 R14.2@229.5,12 R11.2@230.5,12 R10.2@231.5,12 R9.2@232.5,12 R8.2@233.5,12 ; v1(229,24.25) 229,23.05 R66.2@229.05,23 ; R59.1@230.5,28 230.75,27.75 v2(230.75,27) ; v1(233.5,10.75) R8.2@233.5,12 ; R5.2@236.5,12 R6.2@235.5,12 R7.2@234.5,12 R8.2@233.5,12 ; R4.2@239,18 v1(240,18) ; R3.2@239,19.25 v1(240,19.25) R19.2@241.75,19.25
  Top Copper w0.5: v1@198.487,9.237 v1(198.5,9.25) ; v1(198.487,14.25) v1@198.5,14.25
  Copper Layer 2 w0.5: v2(229.25,30) 229.25,28.5 v2(230.75,27)
  Copper Layer 3 w0.5: v1@198.487,11.738 v1@198.5,11.75 ; 230.75,24.25 v2(230.75,27)
  Bottom Copper w0.2: C46.2@197.5,6.625 v1(198.487,6.625) 199.475,6.625 U4.5@199.5,6.65 ; C44.2@197.5,11.75 v1(198.487,11.75) 199.475,11.75 U12.5@199.5,11.775 ; C55.2@197.5,14.25 v1(198.487,14.25) 199.475,14.25 U5.5@199.5,14.275 ; v1(197.75,17) C56.2@198.5,17 198.6,16.9 U7.5@199.5,16.9 ; v1(197.75,22) C43.2@198.5,22 198.6,21.9 U10.5@199.5,21.9 ; U9.5@210.5,19.35 211.6,19.35 C35.2@211.625,19.375 v1(211.625,18.5) ; U8.5@211.125,9.35 211.15,9.375 C37.2@213.125,9.375 ; U13.5@211.125,11.85 211.15,11.875 C36.2@213.125,11.875
  Bottom Copper w0.25: C45.2@197.5,9.25 v1(198.5,9.25) U6.5@199.5,9.25 ; v1(210.125,6.125) 211.1,6.125 U14.5@211.125,6.1 212.1,6.1 C38.2@212.125,6.125 ; v1(240,18) R27.2@241.8,18
  other v1: 212.138,9.375 212.138,11.875
3.3V-4: C106.1 C107.1 C108.1 C109.1 C144.2 C145.2 C206.1 C207.1 C208.1 C209.1 C306.1 C307.1 C308.1 C309.1 J6.2 R100.1 R110.2 R111.2 R112.1 R117.2 R200.1 R210.2 R211.2 R212.1 R217.2 R300.1 R310.2 R311.2 R312.1 R317.2 U100.4 U100.5 U102.5 U103.5 U200.4 U200.5 U300.4 U300.5 | length 90.8
  Top Copper w0.25: v2(23,13.75) 23.925,13.75 R100.1@24.05,13.875 ; v1(24.5,7.625) R117.2@25.5,7.625 ; v1(24.5,10.25) R111.2@25.5,10.25 ; U100.4@32.4,9.75 33.875,9.75 34.25,9.375 C109.1@34.375,9.375 35.325,9.375 C108.1@35.5,9.2 35.575,9.125 v1(36.625,9.125) ; U100.5@32.4,10.25 C107.1@34.375,10.25 35.325,10.25 C106.1@35.5,10.425 35.7,10.625 v1(36.625,10.625) ; R110.2@32.625,5.5 R112.1@33.5,5.5 v1(34.25,5.5) ; v2(83,13.75) 83.925,13.75 R200.1@84.05,13.875 ; v1(84.5,7.625) R217.2@85.5,7.625 ; v1(84.5,10.25) R211.2@85.5,10.25 ; U200.4@92.4,9.75 93.875,9.75 94.25,9.375 95.325,9.375 C206.1@95.5,9.2 95.575,9.125 v1(96.625,9.125) ; U200.5@92.4,10.25 C209.1@94.375,10.25 95.325,10.25 C208.1@95.5,10.425 95.7,10.625 v1(96.625,10.625) ; R210.2@92.625,5.5 R212.1@93.5,5.5 v1(94.25,5.5) ; v2(143,13.75) 143.925,13.75 R300.1@144.05,13.875 ; v1(144.5,7.625) R317.2@145.5,7.625 ; v1(144.5,10.25) R311.2@145.5,10.25 ; U300.4@152.4,9.75 153.875,9.75 154.25,9.375 155.325,9.375 155.575,9.125 v1(156.625,9.125) ; U300.5@152.4,10.25 C307.1@154.375,10.25 155.325,10.25 155.7,10.625 v1(156.625,10.625) ; R310.2@152.625,5.5 R312.1@153.5,5.5 v1(154.25,5.5)
  Copper Layer 3 w0.5: 35.375,13.625 35.25,13.75 v1(35.25,19.75) 35.25,24 v1(36.375,25.125)
  Copper Layer 3 w1: v1@156.5,9.25 160.75,9.25 167.5,2.5 J6.2@186.9,2.5
  Bottom Copper w0.25: v1(35.25,19.75) C145.2@35.25,21.5 35.25,22.475 U102.5@35.375,22.6 ; U103.5@35.375,25.1 37.225,25.1 C144.2@37.25,25.125
3.3V-IO: D700.1 J700.6 J700.8 | length 18.8
  Top Copper w0.25: J700.6@65.4,91.23 65.4,89.85 66.25,89 77,89 78,90 D700.1@78,91.45
  Top Copper w1: J700.8@62.86,91.23 J700.6@65.4,91.23 65.48,91.23 J700.6@65.5,91.25
3.3V-VR6: C13.1 D13.1 J8.2 VR6.4 | length 31.5
  Top Copper w0.2: v1(382.5,25) 383.95,23.55 D13.1@383.95,17.5
  Copper Layer 3 w0.2: v1(368.75,36.5) 368.75,28.75 372.5,25 v1(382.5,25)
  Bottom Copper w0.2: VR6.4@368.75,38 VR6.4@369,38.25
  other v1: 367.25,44.5 368.25,44.5 369.25,44.5 370.25,44.5
12V: C101.1 C124.1 C201.1 C224.1 C301.1 C324.1 C401.1 C424.1 C501.1 C524.1 J4.1 L100.1 L200.1 L300.1 L400.1 L500.1 L600.1 R18.1 R26.1 R49.1 U101.1 U101.22 U201.1 U201.22 U301.1 U301.22 U401.1 U401.22 U501.1 U501.22 | length 115.2
  Top Copper w0.25: C124.1@22,30.3 23.05,30.3 23.333,30.583 U101.1@23.333,31.3 ; U101.22@36.668,31.3 36.668,30.583 36.95,30.3 C101.1@38,30.3 ; C224.1@82,30.3 83.05,30.3 83.333,30.583 U201.1@83.333,31.3 ; U201.22@96.668,31.3 96.668,30.583 96.95,30.3 C201.1@98,30.3 ; C324.1@142,30.3 143.05,30.3 143.332,30.583 U301.1@143.332,31.3 ; U301.22@156.667,31.3 156.667,30.583 156.95,30.3 C301.1@158,30.3 ; R18.1@236.5,10.2 236.55,10.25 v1(237.75,10.25) ; R26.1@236.75,5.2 237.3,5.75 v1(238.25,5.75) ; C424.1@262,30.3 263.05,30.3 263.333,30.583 U401.1@263.333,31.3 ; U401.22@276.668,31.3 276.668,30.583 276.95,30.3 C401.1@278,30.3 ; C524.1@322,30.3 323.05,30.3 323.333,30.583 U501.1@323.333,31.3 ; U501.22@336.668,31.3 336.668,30.583 336.95,30.3 C501.1@338,30.3
  Top Copper w0.5: v1(22,29.25) C124.1@22,30.2 ; C101.1@38,30.25 C101.1@38.05,30.25 ; C101.1@38,30.3 C101.1@38.05,30.25 ; v1(39.125,30.25) C101.1@38.05,30.25 ; L100.1@39.45,27.75 v1(40.5,27.75) ; v1(82,29.25) C224.1@82,30.2 ; C201.1@98,30.25 C201.1@98.05,30.25 ; C201.1@98,30.3 C201.1@98.05,30.25 ; v1(99.125,30.25) C201.1@98.05,30.25 ; L200.1@99.45,27.75 v1(100.5,27.75) ; v1(142,29.25) C324.1@142,30.2 ; C301.1@158,30.25 C301.1@158.05,30.25 ; C301.1@158,30.3 C301.1@158.05,30.25 ; v1(159.125,30.25) C301.1@158.05,30.25 ; L300.1@159.45,27.75 v1(160.5,27.75) ; v1(262,29.25) C424.1@262,30.2 ; C401.1@278,30.25 C401.1@278.05,30.25 ; C401.1@278,30.3 C401.1@278.05,30.25 ; v1(279.125,30.25) C401.1@278.05,30.25 ; L400.1@279.45,27.75 v1(280.5,27.75) ; v1(322,29.25) C524.1@322,30.2 ; C501.1@338,30.25 C501.1@338.05,30.25 ; C501.1@338,30.3 C501.1@338.05,30.25 ; v1(339.125,30.25) C501.1@338.05,30.25 ; L500.1@339.45,27.75 v1(340.5,27.75)
  Copper Layer 3 w0.5: v1(22,29.25) 22.75,30 23,30 ; v1(40.5,27.75) 40.5,30.25 ; v1(82,29.25) 82,30.25 ; v1(100.5,27.75) 100.5,30 ; v1(142,29.25) 142,30.25 ; v1(160.5,27.75) 160.5,30 ; v1(238.25,5.75) 237.75,6.25 v1(237.75,10.25) 243.75,16.25 243.75,29
  Copper Layer 3 w0.75: J4.1@242.493,63.943 242.493,60.007 244,58.5 244,32.25
  Bottom Copper w0.5: L600.1@241,69.35 241,65.436 J4.1@242.493,63.943
  other v1: 362.75,54.5 363.75,54.5 362.75,55.5 363.75,55.5
12V-DC: J2.2 J2.4 J5.2 | length 8.6
  Top Copper w0.75: J2.4@191.27,76.69 J2.2@191.27,79.23 194.54,82.5 J5.2@195.85,82.5 J5.2@196,82.5
12V-IO: J700.2 J700.4 L700.1
12V-OA: C617.1 C618.1 C619.1 L600.2 R610.1 U601.8 | length 27.4
  Copper Layer 3 w0.5: v2(221,72) v2(238.25,72)
  Bottom Copper w0.25: R610.1@237,70.5 C617.1@237,72
  Bottom Copper w0.5: v2(221,72) 222.5,72 222.55,71.95 C619.1@224,71.95 ; C619.1@224,72 224.095,71.905 U601.8@225.525,71.905 ; C617.1@237,72 v2(238.25,72) 240.85,72 L600.2@241,72.15
12V-OA-IO: C710.1 C711.1 C712.1 C717.2 C718.2 C719.2 C720.2 C721.2 C722.2 C723.2 C724.2 C725.2 C726.2 C757.2 C758.2 C759.2 C760.2 C761.2 C762.2 C763.2 C764.2 C765.2 C766.2 L700.2 R740.1 R741.1 U700.8 U701.8 U702.8 U703.8 U704.8 U705.8 U706.8 U707.8 U708.8 U709.8 | length 40.6
  Bottom Copper w0.25: U704.8@14.725,102.095 15.905,102.095 C761.2@16,102 17.2,102 C721.2@17.25,101.95 17.3,102 v2(18.5,102) ; U709.8@14.725,119.595 15.905,119.595 C766.2@16,119.5 17.2,119.5 C726.2@17.25,119.45 17.3,119.5 v2(18.5,119.5) ; U703.8@29.725,102.095 30.905,102.095 C760.2@31,102 32.2,102 C720.2@32.25,101.95 32.3,102 v2(33.5,102) ; U708.8@29.725,119.595 30.905,119.595 C765.2@31,119.5 32.2,119.5 C725.2@32.25,119.45 32.3,119.5 v2(33.5,119.5) ; U702.8@44.725,102.095 45.905,102.095 C759.2@46,102 47.2,102 C719.2@47.25,101.95 47.3,102 v2(48.5,102) ; U707.8@44.725,119.595 45.905,119.595 C764.2@46,119.5 47.2,119.5 C724.2@47.25,119.45 47.3,119.5 v2(48.5,119.5) ; U701.8@59.725,102.095 60.905,102.095 C758.2@61,102 62.2,102 C718.2@62.25,101.95 62.3,102 v2(63.5,102) ; U706.8@59.725,119.595 60.905,119.595 C763.2@61,119.5 62.2,119.5 C723.2@62.25,119.45 62.3,119.5 v2(63.5,119.5) ; v2(73.25,108.5) R740.1@74.25,108.5 ; v2(73.25,126) R741.1@74.25,126 ; U700.8@74.725,102.095 75.905,102.095 C757.2@76,102 77.2,102 C717.2@77.25,101.95 77.3,102 v2(78.5,102) ; U705.8@74.725,119.595 75.905,119.595 C762.2@76,119.5 77.2,119.5 C722.2@77.25,119.45 77.3,119.5 v2(78.5,119.5)
  other v2: 73.75,95.25 75,95.25 73.75,96.25 75,96.25 73.75,97.25 75,97.25 73.75,98.25 75,98.25
12V-VR2: C11.1 C12.1 C16.2 R49.2 VR2.3 VR6.3
  other v1: 370.5,46.75 370.5,48 371.5,49.25
12V-VR3: C17.1 C18.1 C22.2 C23.1 VR3.3 VR4.3 VR5.3
  other v1: 377,14.25 377,15.25 374.25,16.25 375.5,16.75 374.25,28 373.25,28.5 374.25,29 374.25,30
15V: C3.1 C4.1 C14.1 C15.1 C20.1 C21.1 L1.2 R34.2 VR2.1 VR3.1 | length 16.3
  Copper Layer 3 w0.5: v2(388.25,82) 388.25,80.5 392,76.75 v2(392,68.5)
  Bottom Copper w0.5: R34.2@387,82.075 387.075,82 v2(388.25,82)
  other v1: 374.5,39 375.5,39 374.5,40.25 369.5,61.5 370.5,61.5 369.5,62.75
  other v2: 392,65 394,65 381,66.5 384,66.5 385.75,66.75 388.25,66.75 394,68.5 381,69 384,69
\AMP-RESET1: R54.1 U1.2 U101.5 | length 238.9
  Top Copper w0.2: v1(227.5,27) 228.75,27 229.5,26.25 231.5,26.25 232.3,27.05 U1.2@232.3,29.2
  Top Copper w0.25: v1(24.25,25.25) 25.873,26.873 U101.5@25.873,31.2 U101.5@25.873,31.3
  Copper Layer 3 w0.2: v1(28,22.75) 32,22.75 35.25,26 77.5,26 78.375,25.125 78.5,25 82,25 83.75,23.25 88.25,23.25 94.75,16.75 177,16.75 184.25,24 v1(186.25,24) ; v1(186.25,31.25) 187.467,32.467 191.533,32.467 192.75,31.25 211.75,31.25 212.75,30.25 222.25,30.25 222.5,30 222.5,28 223.5,27 v1(227.5,27)
  Bottom Copper w0.2: v1(24.25,25.25) R54.1@25.3,25.25 25.3,23.7 26.25,22.75 v1(28,22.75) ; v1(186.25,24) v1(186.25,31.25)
